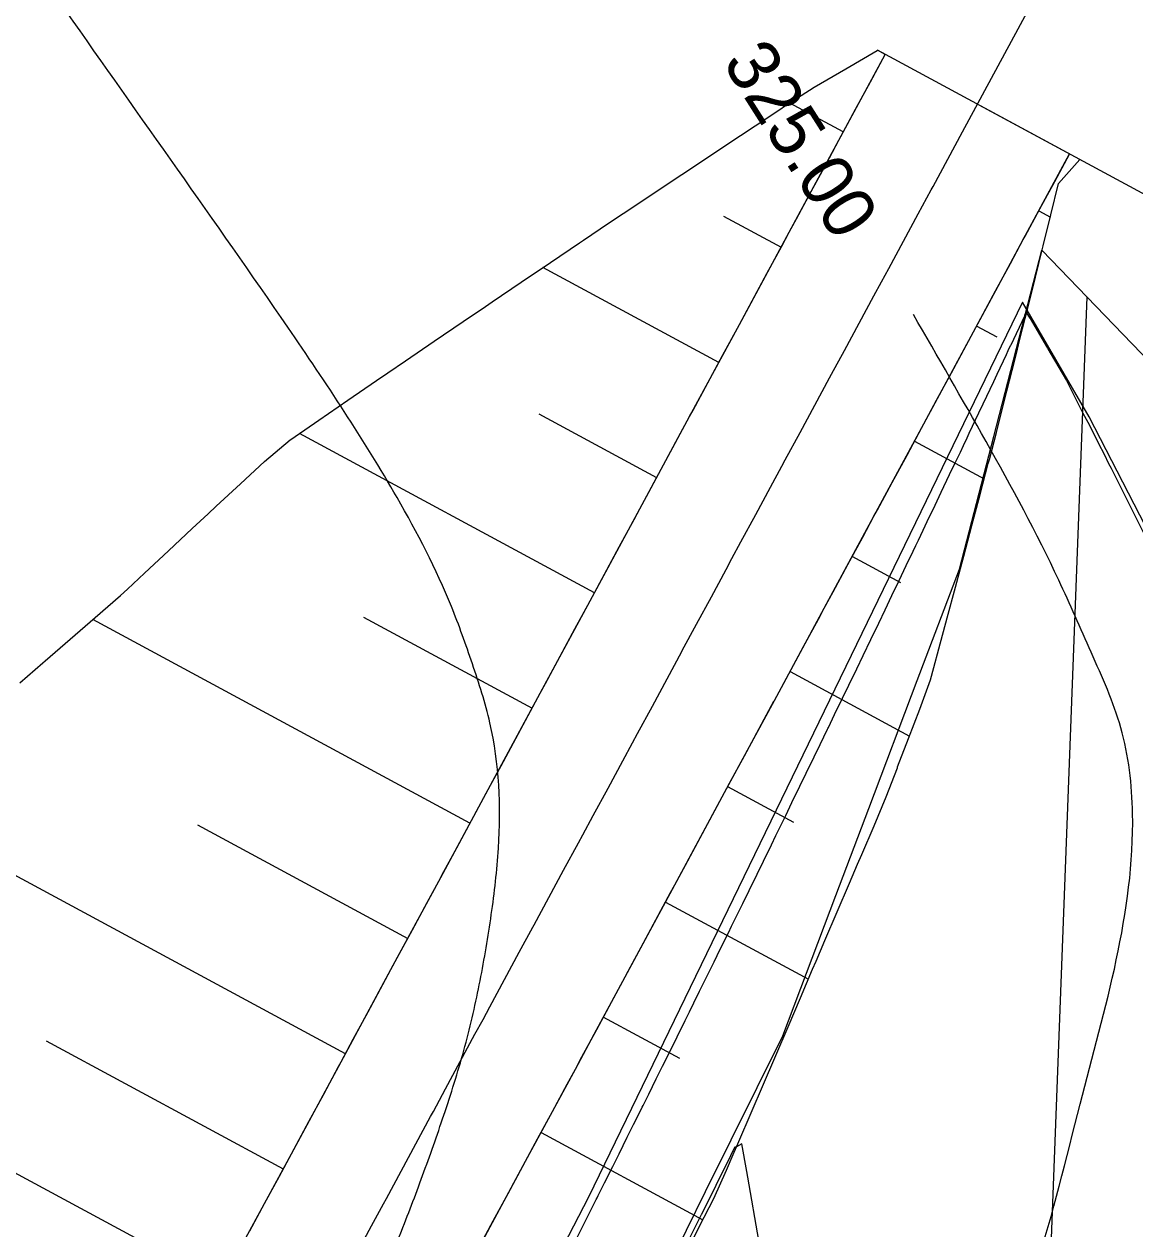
# Model space of a CAD drawing. Extents: x -564043 to -563833, y -1163561 to -1163412.
# Drawn here: x -563969.7 to -563959.09, y -1163473.83 to -1163462.33 of the extents above; entities that cross this region are included whole.
import ezdxf

# ---------------------------------------------------------------- set-up
doc = ezdxf.new("R2010")
doc.units = 0
for name, color, linetype in [('_popis staničení PH1', 7, 'Continuous'), ('Default', 7, 'Continuous'), ('Line', 7, 'Continuous'), ('Vrstva 24', 7, 'Continuous'), ('Vrstva 25', 7, 'Continuous'), ('Vrstva 26', 7, 'Continuous')]:
    doc.layers.add(name, color=color, linetype=linetype)

msp = doc.modelspace()

# ---------------------------------------------------------------- linework, layer by layer
for points in [[(-563966.521, -1163474.062), (-563966.38, -1163473.801), (-563966.265, -1163473.59), (-563966.239, -1163473.54), (-563966.098, -1163473.279), (-563965.957, -1163473.018), (-563965.816, -1163472.757), (-563965.79, -1163472.71), (-563965.675, -1163472.495), (-563965.534, -1163472.234), (-563965.393, -1163471.973), (-563965.315, -1163471.83), (-563965.252, -1163471.712), (-563965.111, -1163471.451), (-563964.97, -1163471.19), (-563964.84, -1163470.95), (-563964.829, -1163470.929), (-563964.688, -1163470.667), (-563964.547, -1163470.406), (-563964.406, -1163470.145), (-563964.365, -1163470.07), (-563964.265, -1163469.884), (-563964.123, -1163469.623), (-563963.982, -1163469.362), (-563963.89, -1163469.19), (-563963.841, -1163469.1), (-563963.7, -1163468.839), (-563963.559, -1163468.578), (-563963.418, -1163468.317), (-563963.415, -1163468.31), (-563963.277, -1163468.056), (-563963.136, -1163467.795), (-563962.995, -1163467.534), (-563962.94, -1163467.43), (-563962.854, -1163467.272), (-563962.713, -1163467.011), (-563962.572, -1163466.75), (-563962.464, -1163466.55), (-563962.431, -1163466.489), (-563962.29, -1163466.228), (-563962.149, -1163465.967), (-563962.008, -1163465.706), (-563961.989, -1163465.67), (-563961.867, -1163465.444), (-563961.726, -1163465.183), (-563961.585, -1163464.922), (-563961.514, -1163464.79), (-563961.444, -1163464.661), (-563961.303, -1163464.4), (-563961.162, -1163464.139), (-563961.039, -1163463.911), (-563961.021, -1163463.878), (-563960.88, -1163463.616), (-563960.739, -1163463.355), (-563956.21, -1163454.967)], [(-563969.736, -1163468.616), (-563969.517, -1163468.425), (-563969.497, -1163468.407), (-563969.258, -1163468.2), (-563969.018, -1163467.992), (-563968.777, -1163467.784), (-563968.71, -1163467.724), (-563968.548, -1163467.571), (-563968.319, -1163467.357), (-563968.091, -1163467.143), (-563967.94, -1163467.003), (-563967.862, -1163466.93), (-563967.632, -1163466.716), (-563967.402, -1163466.503), (-563967.157, -1163466.298), (-563967.15, -1163466.293), (-563966.883, -1163466.109), (-563966.608, -1163465.92), (-563966.333, -1163465.731), (-563966.224, -1163465.657), (-563966.057, -1163465.543), (-563965.782, -1163465.355), (-563965.505, -1163465.167), (-563965.293, -1163465.023), (-563965.228, -1163464.979), (-563964.951, -1163464.791), (-563964.673, -1163464.604), (-563964.395, -1163464.417), (-563964.358, -1163464.392), (-563964.117, -1163464.23), (-563963.838, -1163464.043), (-563963.558, -1163463.857), (-563963.417, -1163463.763), (-563963.279, -1163463.671), (-563962.998, -1163463.485), (-563962.718, -1163463.299), (-563962.472, -1163463.137), (-563962.437, -1163463.113), (-563962.154, -1163462.929), (-563961.854, -1163462.754), (-563961.553, -1163462.579), (-563961.551, -1163462.577)], [(-563969.736, -1163468.616), (-563969.517, -1163468.425), (-563969.497, -1163468.407), (-563969.258, -1163468.2), (-563969.018, -1163467.992), (-563968.777, -1163467.784), (-563968.71, -1163467.724), (-563968.548, -1163467.571), (-563968.319, -1163467.357), (-563968.091, -1163467.143), (-563967.94, -1163467.003), (-563967.862, -1163466.93), (-563967.632, -1163466.716), (-563967.402, -1163466.503), (-563967.157, -1163466.298), (-563967.15, -1163466.293), (-563966.883, -1163466.109), (-563966.608, -1163465.92), (-563966.333, -1163465.731), (-563966.224, -1163465.657), (-563966.057, -1163465.543), (-563965.782, -1163465.355), (-563965.505, -1163465.167), (-563965.293, -1163465.023), (-563965.228, -1163464.979), (-563964.951, -1163464.791), (-563964.673, -1163464.604), (-563964.395, -1163464.417), (-563964.358, -1163464.392), (-563964.117, -1163464.23), (-563963.838, -1163464.043), (-563963.558, -1163463.857), (-563963.417, -1163463.763), (-563963.279, -1163463.671), (-563962.998, -1163463.485), (-563962.718, -1163463.299), (-563962.472, -1163463.137), (-563962.437, -1163463.113), (-563962.154, -1163462.929), (-563961.854, -1163462.754), (-563961.553, -1163462.579), (-563961.551, -1163462.577)], [(-563967.621, -1163473.994), (-563967.145, -1163473.115), (-563966.67, -1163472.235), (-563966.195, -1163471.355), (-563966.014, -1163471.02), (-563965.72, -1163470.475), (-563965.245, -1163469.595), (-563964.77, -1163468.715), (-563964.295, -1163467.835), (-563963.82, -1163466.955), (-563963.344, -1163466.075), (-563962.869, -1163465.195), (-563962.394, -1163464.315), (-563962.159, -1163463.88), (-563961.919, -1163463.435), (-563961.477, -1163462.617)], [(-563967.542, -1163473.848), (-563967.401, -1163473.587), (-563967.26, -1163473.326), (-563967.145, -1163473.115), (-563967.119, -1163473.065), (-563966.978, -1163472.804), (-563966.837, -1163472.543), (-563966.696, -1163472.281), (-563966.67, -1163472.235), (-563966.555, -1163472.02), (-563966.414, -1163471.759), (-563966.273, -1163471.498), (-563966.195, -1163471.355), (-563966.132, -1163471.237), (-563965.99, -1163470.976), (-563965.849, -1163470.715), (-563965.72, -1163470.475), (-563965.708, -1163470.453), (-563965.567, -1163470.192), (-563965.426, -1163469.931), (-563965.285, -1163469.67), (-563965.245, -1163469.595), (-563965.144, -1163469.409), (-563965.003, -1163469.148), (-563964.862, -1163468.887), (-563964.77, -1163468.715), (-563964.721, -1163468.625), (-563964.58, -1163468.364), (-563964.439, -1163468.103), (-563964.298, -1163467.842), (-563964.295, -1163467.835), (-563964.157, -1163467.581), (-563964.016, -1163467.32), (-563963.875, -1163467.058), (-563963.82, -1163466.955), (-563963.734, -1163466.797), (-563963.593, -1163466.536), (-563963.452, -1163466.275), (-563963.344, -1163466.075), (-563963.311, -1163466.014), (-563963.17, -1163465.753), (-563963.029, -1163465.492), (-563962.888, -1163465.23), (-563962.869, -1163465.195), (-563962.747, -1163464.969), (-563962.606, -1163464.708), (-563962.465, -1163464.447), (-563962.394, -1163464.315), (-563962.324, -1163464.186), (-563962.183, -1163463.925), (-563962.042, -1163463.664), (-563961.919, -1163463.435), (-563961.901, -1163463.402), (-563961.76, -1163463.141), (-563961.619, -1163462.88), (-563961.478, -1163462.619), (-563961.477, -1163462.617)], [(-563959.822, -1163463.85), (-563959.62, -1163463.622), (-563959.618, -1163463.621), (-563961.551, -1163462.577)], [(-563965.386, -1163474.065), (-563964.91, -1163473.185), (-563964.435, -1163472.305), (-563964.255, -1163471.97), (-563963.96, -1163471.425), (-563963.485, -1163470.545), (-563963.01, -1163469.665), (-563962.535, -1163468.785), (-563962.06, -1163467.905), (-563961.585, -1163467.025), (-563961.109, -1163466.146), (-563960.634, -1163465.266), (-563960.399, -1163464.83), (-563960.159, -1163464.386), (-563959.717, -1163463.568)], [(-563965.359, -1163474.015), (-563965.218, -1163473.754), (-563965.077, -1163473.493), (-563964.936, -1163473.232), (-563964.91, -1163473.185), (-563964.795, -1163472.971), (-563964.654, -1163472.709), (-563964.513, -1163472.448), (-563964.435, -1163472.305), (-563964.372, -1163472.187), (-563964.231, -1163471.926), (-563964.09, -1163471.665), (-563963.96, -1163471.425), (-563963.949, -1163471.404), (-563963.808, -1163471.142), (-563963.667, -1163470.881), (-563963.526, -1163470.62), (-563963.485, -1163470.545), (-563963.385, -1163470.359), (-563963.244, -1163470.098), (-563963.103, -1163469.837), (-563963.01, -1163469.665), (-563962.962, -1163469.576), (-563962.821, -1163469.314), (-563962.68, -1163469.053), (-563962.539, -1163468.792), (-563962.535, -1163468.785), (-563962.398, -1163468.531), (-563962.257, -1163468.27), (-563962.115, -1163468.009), (-563962.06, -1163467.905), (-563961.974, -1163467.748), (-563961.833, -1163467.486), (-563961.692, -1163467.225), (-563961.585, -1163467.025), (-563961.551, -1163466.964), (-563961.41, -1163466.703), (-563961.269, -1163466.442), (-563961.128, -1163466.181), (-563961.109, -1163466.146), (-563960.987, -1163465.92), (-563960.846, -1163465.658), (-563960.705, -1163465.397), (-563960.634, -1163465.266), (-563960.564, -1163465.136), (-563960.423, -1163464.875), (-563960.282, -1163464.614), (-563960.159, -1163464.386), (-563960.141, -1163464.353), (-563960, -1163464.092), (-563959.859, -1163463.83), (-563959.718, -1163463.569), (-563959.717, -1163463.568)], [(-563959.822, -1163463.85), (-563959.62, -1163463.622), (-563959.618, -1163463.621)], [(-563963.359, -1163474.023), (-563963.249, -1163473.805), (-563963.114, -1163473.541), (-563962.993, -1163473.269), (-563962.928, -1163473.119), (-563962.875, -1163472.995), (-563962.757, -1163472.722), (-563962.639, -1163472.448), (-563962.531, -1163472.197), (-563962.522, -1163472.174), (-563962.404, -1163471.9), (-563962.287, -1163471.626), (-563962.17, -1163471.352), (-563962.137, -1163471.273), (-563962.053, -1163471.078), (-563961.937, -1163470.804), (-563961.819, -1163470.53), (-563961.741, -1163470.35), (-563961.701, -1163470.257), (-563961.582, -1163469.983), (-563961.469, -1163469.707), (-563961.361, -1163469.428), (-563961.359, -1163469.42), (-563961.254, -1163469.148), (-563961.147, -1163468.869), (-563961.044, -1163468.587), (-563961.013, -1163468.471), (-563960.965, -1163468.293), (-563960.886, -1163467.998), (-563960.807, -1163467.704), (-563960.746, -1163467.478), (-563960.728, -1163467.409), (-563960.649, -1163467.114), (-563960.571, -1163466.819), (-563960.493, -1163466.524), (-563960.483, -1163466.484), (-563960.415, -1163466.228), (-563960.341, -1163465.932), (-563960.266, -1163465.635), (-563960.228, -1163465.485), (-563960.192, -1163465.337), (-563960.117, -1163465.04), (-563960.043, -1163464.743), (-563959.979, -1163464.483), (-563959.969, -1163464.445), (-563959.896, -1163464.148), (-563959.822, -1163463.85)], [(-563963.359, -1163474.023), (-563963.249, -1163473.805), (-563963.114, -1163473.541), (-563962.993, -1163473.269), (-563962.928, -1163473.119), (-563962.875, -1163472.995), (-563962.757, -1163472.722), (-563962.639, -1163472.448), (-563962.531, -1163472.197), (-563962.522, -1163472.174), (-563962.404, -1163471.9), (-563962.287, -1163471.626), (-563962.17, -1163471.352), (-563962.137, -1163471.273), (-563962.053, -1163471.078), (-563961.937, -1163470.804), (-563961.819, -1163470.53), (-563961.741, -1163470.35), (-563961.701, -1163470.257), (-563961.582, -1163469.983), (-563961.469, -1163469.707), (-563961.361, -1163469.428), (-563961.359, -1163469.42), (-563961.254, -1163469.148), (-563961.147, -1163468.869), (-563961.044, -1163468.587), (-563961.013, -1163468.471), (-563960.965, -1163468.293), (-563960.886, -1163467.998), (-563960.807, -1163467.704), (-563960.746, -1163467.478), (-563960.728, -1163467.409), (-563960.649, -1163467.114), (-563960.571, -1163466.819), (-563960.493, -1163466.524), (-563960.483, -1163466.484), (-563960.415, -1163466.228), (-563960.341, -1163465.932), (-563960.266, -1163465.635), (-563960.228, -1163465.485), (-563960.192, -1163465.337), (-563960.117, -1163465.04), (-563960.043, -1163464.743), (-563959.979, -1163464.483), (-563959.969, -1163464.445), (-563959.896, -1163464.148), (-563959.822, -1163463.85)], [(-563969.513, -1163486.248), (-563968.702, -1163484.611), (-563968.142, -1163483.478), (-563966.349, -1163479.855), (-563965.958, -1163479.067), (-563964.584, -1163476.289), (-563963.373, -1163473.843), (-563963.192, -1163473.475), (-563963.191, -1163473.474), (-563962.456, -1163471.989), (-563961.948, -1163470.647), (-563961.634, -1163469.818), (-563961.634, -1163469.816), (-563961.172, -1163468.595), (-563960.769, -1163467.532), (-563960.441, -1163466.264), (-563959.982, -1163464.487), (-563959.119, -1163465.38), (-563958.498, -1163466.022)], [(-563962.682, -1163473.94), (-563962.788, -1163473.337), (-563962.798, -1163473.283), (-563962.845, -1163473.017), (-563962.896, -1163473.046), (-563962.913, -1163473.05), (-563962.943, -1163473.111), (-563962.943, -1163473.111), (-563962.955, -1163473.134), (-563962.955, -1163473.135), (-563963.094, -1163473.413), (-563963.095, -1163473.416), (-563963.232, -1163473.692), (-563963.234, -1163473.695), (-563963.371, -1163473.97)]]:
    msp.add_lwpolyline(points)
msp.add_lwpolyline([(-563976.663, -1163501.462), (-563964.742, -1163493.091), (-563961.829, -1163491.15), (-563957.41, -1163486.988), (-563956.735, -1163486.627), (-563953.281, -1163481.221), (-563953.993, -1163478.343), (-563957.796, -1163470.824), (-563957.81, -1163470.439), (-563957.835, -1163469.754), (-563958.239, -1163469.063), (-563958.187, -1163468.683), (-563959.529, -1163466.077), (-563960.166, -1163464.984), (-563964.31, -1163473.527), (-563966.903, -1163478.544), (-563968.406, -1163481.669), (-563970.316, -1163485.955), (-563973.278, -1163492.988), (-563976.735, -1163500.155), (-563977.161, -1163500.889), (-563977.363, -1163501.307)], close=True)
at = {"layer": '_popis staničení PH1'}
msp.add_lwpolyline([(-563960.584, -1163463.099), (-563944.707, -1163471.673)], dxfattribs=at)
at = {"layer": 'Default'}
msp.add_lwpolyline([(-563964.434, -1163473.946), (-563964.357, -1163473.791), (-563964.303, -1163473.685), (-563964.236, -1163473.549), (-563964.228, -1163473.533), (-563964.218, -1163473.513), (-563964.157, -1163473.391), (-563964.078, -1163473.235), (-563964.018, -1163473.114), (-563963.94, -1163472.956), (-563963.879, -1163472.835), (-563963.801, -1163472.677), (-563963.796, -1163472.667), (-563963.789, -1163472.654), (-563963.734, -1163472.543), (-563963.663, -1163472.399), (-563963.602, -1163472.277), (-563963.525, -1163472.12), (-563963.464, -1163471.998), (-563963.387, -1163471.841), (-563963.369, -1163471.804), (-563963.345, -1163471.757), (-563963.303, -1163471.672), (-563963.249, -1163471.561), (-563963.189, -1163471.439), (-563963.111, -1163471.282), (-563963.051, -1163471.16), (-563962.974, -1163471.003), (-563962.943, -1163470.94), (-563962.904, -1163470.859), (-563962.875, -1163470.8), (-563962.837, -1163470.723), (-563962.777, -1163470.6), (-563962.7, -1163470.444), (-563962.64, -1163470.321), (-563962.564, -1163470.164), (-563962.52, -1163470.075), (-563962.464, -1163469.96), (-563962.448, -1163469.927), (-563962.427, -1163469.884), (-563962.368, -1163469.761), (-563962.291, -1163469.604), (-563962.232, -1163469.481), (-563962.155, -1163469.324), (-563962.099, -1163469.207), (-563962.027, -1163469.059), (-563962.024, -1163469.052), (-563962.02, -1163469.043), (-563961.96, -1163468.919), (-563961.884, -1163468.763), (-563961.824, -1163468.638), (-563961.749, -1163468.483), (-563961.688, -1163468.355), (-563961.614, -1163468.202), (-563961.604, -1163468.182), (-563961.593, -1163468.158), (-563961.539, -1163468.047), (-563961.479, -1163467.921), (-563961.414, -1163467.784), (-563961.345, -1163467.64), (-563961.276, -1163467.497), (-563961.21, -1163467.359), (-563961.185, -1163467.306), (-563961.16, -1163467.255), (-563961.116, -1163467.161), (-563961.076, -1163467.078), (-563961.001, -1163466.92), (-563960.942, -1163466.797), (-563960.863, -1163466.629), (-563960.809, -1163466.516), (-563960.76, -1163466.414), (-563960.73, -1163466.35), (-563960.696, -1163466.277), (-563960.675, -1163466.234), (-563960.583, -1163466.04), (-563960.542, -1163465.953), (-563960.441, -1163465.739), (-563960.409, -1163465.671), (-563960.321, -1163465.483), (-563960.303, -1163465.445), (-563960.28, -1163465.398), (-563960.276, -1163465.389), (-563960.146, -1163465.112), (-563960.144, -1163465.107), (-563960.131, -1163465.079), (-563960.127, -1163465.084), (-563960.108, -1163465.118), (-563960.096, -1163465.137), (-563960.094, -1163465.14), (-563959.928, -1163465.421), (-563959.903, -1163465.465), (-563959.819, -1163465.606), (-563959.746, -1163465.731), (-563959.59, -1163466.042), (-563959.542, -1163466.129), (-563959.531, -1163466.151), (-563959.504, -1163466.204), (-563959.476, -1163466.26), (-563959.44, -1163466.331), (-563959.388, -1163466.435), (-563959.345, -1163466.522), (-563959.321, -1163466.569), (-563958.779, -1163467.65)], dxfattribs=at)
at = {"layer": 'Line'}
for p, q in [((-563961.477, -1163462.617), (-563961.551, -1163462.577)), ((-563961.877, -1163463.358), (-563962.389, -1163463.082)), ((-563960.011, -1163464.111), (-563959.901, -1163464.17)), ((-563963.021, -1163464.162), (-563962.471, -1163464.458)), ((-563963.065, -1163465.558), (-563964.744, -1163464.652)), ((-563959.553, -1163464.931), (-563960.089, -1163479.118)), ((-563960.409, -1163465.316), (-563960.605, -1163465.211)), ((-563964.785, -1163466.05), (-563963.659, -1163466.658)), ((-563964.253, -1163467.758), (-563967.069, -1163466.238)), ((-563961.199, -1163466.311), (-563960.532, -1163466.671)), ((-563961.328, -1163467.661), (-563961.792, -1163467.41)), ((-563965.441, -1163469.958), (-563969.042, -1163468.013)), ((-563966.456, -1163467.989), (-563964.847, -1163468.858)), ((-563962.386, -1163468.51), (-563961.246, -1163469.126)), ((-563962.348, -1163469.952), (-563962.98, -1163469.61)), ((-563966.629, -1163472.158), (-563970.976, -1163469.81)), ((-563968.042, -1163469.974), (-563966.035, -1163471.058)), ((-563963.574, -1163470.71), (-563962.21, -1163471.447)), ((-563967.817, -1163474.357), (-563972.52, -1163471.82)), ((-563963.436, -1163472.205), (-563964.168, -1163471.81)), ((-563969.486, -1163472.035), (-563967.223, -1163473.258)), ((-563964.762, -1163472.91), (-563963.218, -1163473.744))]:
    msp.add_line(p, q, dxfattribs=at)
at = {"layer": 'Vrstva 24'}
msp.add_spline([(-563948.938, -1163476.52), (-563948.45, -1163475.26), (-563947.979, -1163473.791), (-563947.826, -1163473.055), (-563947.76, -1163472.318), (-563947.801, -1163472.127), (-563947.912, -1163471.854), (-563948.426, -1163470.488), (-563948.923, -1163469.115), (-563949.425, -1163467.743), (-563949.955, -1163466.38), (-563952.19, -1163462.283), (-563953.432, -1163460.556), (-563954.94, -1163458.55), (-563956.468, -1163456.56), (-563957.991, -1163454.564), (-563959.48, -1163452.54), (-563962.42, -1163447.812), (-563963.74, -1163445.355), (-563965.037, -1163442.878), (-563965.052, -1163442.844), (-563965.079, -1163442.739), (-563965.877, -1163440.223)], degree=3, dxfattribs=at)
at = {"layer": 'Vrstva 25'}
msp.add_spline([(-563979.181, -1163499.008), (-563978.428, -1163498.506), (-563977.533, -1163497.79), (-563971.745, -1163492.882), (-563969.933, -1163491.157), (-563968.824, -1163489.747), (-563966.163, -1163485.494), (-563965.399, -1163484.181), (-563964.1, -1163481.868), (-563961.431, -1163477.021), (-563960.731, -1163475.725), (-563960.044, -1163474.189), (-563959.617, -1163472.641), (-563959.116, -1163469.866), (-563959.228, -1163469.046), (-563959.512, -1163468.326), (-563959.82, -1163467.638), (-563960.515, -1163466.313), (-563961.208, -1163465.1)], degree=3, dxfattribs=at)
at = {"layer": 'Vrstva 26'}
for points in [[(-563953.526, -1163471.899), (-563953.567, -1163470.507), (-563953.958, -1163469.011), (-563954.848, -1163467.214), (-563956.699, -1163463.764), (-563958.533, -1163460.754), (-563960.868, -1163457.479), (-563965.71, -1163450.849), (-563966.353, -1163449.887), (-563966.647, -1163449.387), (-563966.923, -1163448.875), (-563967.652, -1163447.026), (-563967.841, -1163446.363), (-563968.015, -1163445.697), (-563968.19, -1163445.031), (-563968.38, -1163444.369), (-563968.898, -1163442.86), (-563969.474, -1163441.631), (-563972.038, -1163435.816), (-563972.223, -1163435.346)], [(-563972.104, -1163483.444), (-563971.432, -1163482.54), (-563969.672, -1163480.022), (-563968.003, -1163477.443), (-563966.946, -1163475.644), (-563966.582, -1163474.952), (-563966.094, -1163473.851), (-563965.88, -1163473.286), (-563965.678, -1163472.709), (-563965.489, -1163472.088), (-563965.344, -1163471.461), (-563965.237, -1163470.83), (-563965.169, -1163470.196), (-563965.25, -1163468.999), (-563965.418, -1163468.435), (-563965.618, -1163467.888), (-563966.136, -1163466.849), (-563967.179, -1163465.223), (-563969.294, -1163462.205), (-563970.81, -1163460.003), (-563971.343, -1163459.213), (-563971.719, -1163458.626), (-563972.18, -1163457.904), (-563973.29, -1163456.114), (-563973.826, -1163455.207), (-563974.35, -1163454.292), (-563975.821, -1163451.273), (-563976.512, -1163449.594), (-563977.063, -1163448.162), (-563977.464, -1163447.121)]]:
    msp.add_spline(points, degree=3, dxfattribs=at)

# ---------------------------------------------------------------- texts
at = {"layer": 'Vrstva 25'}
msp.add_text('325.00', height=0.5, rotation=302.4321, dxfattribs=at).set_placement((-563963.038, -1163462.695))

doc.saveas('drawing.dxf')
